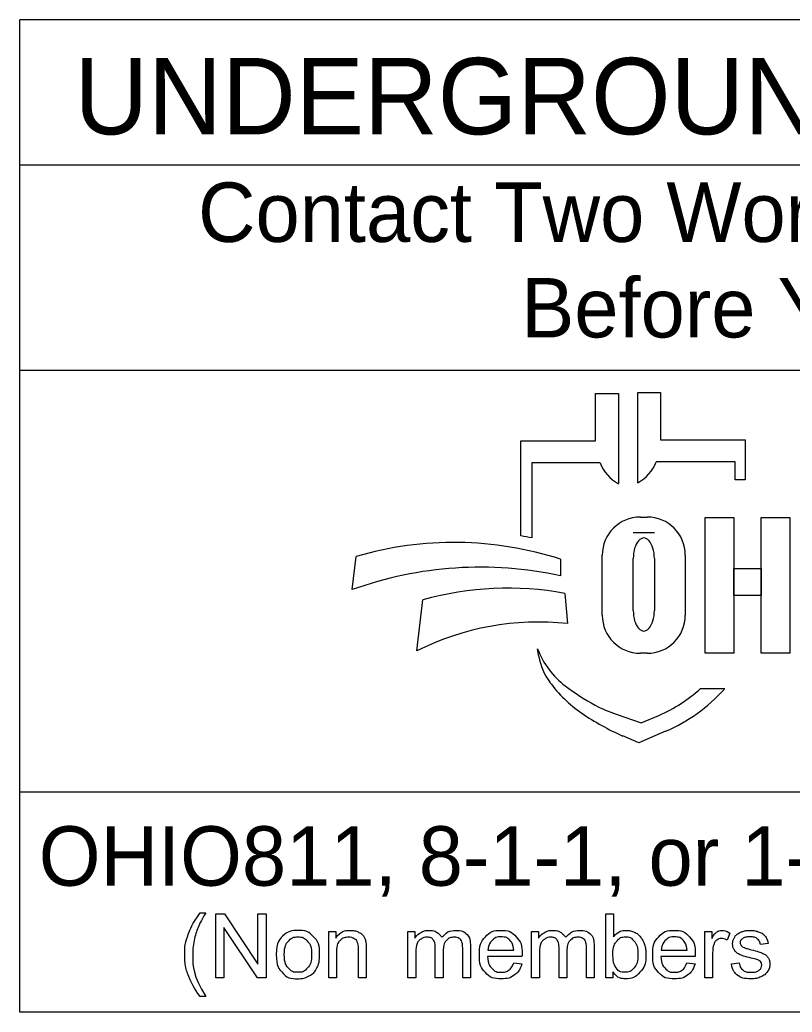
# Model space of a CAD drawing. Extents: x 0 to 42.4, y 0 to 22.
# Drawn here: x 3.947 to 5.766, y 2.954 to 5.292 of the extents above; entities that cross this region are included whole.
import ezdxf

# ---------------------------------------------------------------- set-up
doc = ezdxf.new("R2010")
doc.units = 0
doc.layers.add('SH_Data', color=7, linetype='Continuous')
doc.layers.add('SH_Text', color=7, linetype='Continuous')

msp = doc.modelspace()

# ---------------------------------------------------------------- linework, layer by layer
at = {"layer": 'SH_Data'}
for p, q in [((3.9472, 2.9543), (3.9472, 5.2918)), ((8.1972, 5.2918), (3.9472, 5.2918)), ((3.9472, 4.9502), (8.1972, 4.9502)), ((3.9472, 4.4668), (8.1972, 4.4668)), ((8.1972, 3.4721), (3.9472, 3.4721)), ((8.1972, 2.9543), (3.9472, 2.9543))]:
    msp.add_line(p, q, dxfattribs=at)
at = {"layer": 'SH_Text'}
for p, q in [((5.3032, 4.2998), (5.3032, 4.4112)), ((5.3032, 4.4112), (5.3569, 4.4112)), ((5.3569, 4.4112), (5.3569, 4.1992)), ((5.4026, 4.2015), (5.4026, 4.4136)), ((5.4026, 4.4136), (5.4562, 4.4136)), ((5.4562, 4.4136), (5.4562, 4.3021)), ((5.4562, 4.3021), (5.6554, 4.3021)), ((5.6554, 4.3021), (5.6554, 4.2083)), ((5.1273, 4.0759), (5.1273, 4.2998)), ((5.1273, 4.2998), (5.3032, 4.2998)), ((5.1525, 4.2483), (5.1525, 4.0715)), ((5.3136, 4.2483), (5.1525, 4.2483)), ((5.6321, 4.2506), (5.4458, 4.2506)), ((5.6321, 4.2083), (5.6321, 4.2506)), ((5.6554, 4.2083), (5.6321, 4.2083)), ((5.4082, 4.1206), (5.4248, 4.1206)), ((5.4415, 4.0836), (5.3917, 4.0836)), ((4.7299, 3.9496), (4.7393, 4.0277)), ((5.2206, 4.0212), (5.2206, 3.9824)), ((5.3188, 3.8891), (5.3188, 4.0311)), ((5.3917, 3.9005), (5.3917, 4.0228)), ((5.4415, 4.0228), (5.4415, 3.9005)), ((5.5142, 4.0311), (5.5142, 3.8891)), ((5.2305, 3.9406), (5.2368, 3.8696)), ((4.8817, 3.805), (4.8964, 3.9252)), ((5.1694, 3.7921), (5.1664, 3.8101)), ((5.4248, 3.7996), (5.4082, 3.7996)), ((5.5497, 3.7163), (5.6071, 3.7163)), ((5.3513, 3.6559), (5.4107, 3.6354)), ((5.4107, 3.6354), (5.4518, 3.6532)), ((5.4047, 3.5884), (5.3673, 3.6048)), ((5.468, 3.6158), (5.4047, 3.5884))]:
    msp.add_line(p, q, dxfattribs=at)
for points in [[(5.5607, 4.1195), (5.6286, 4.1195), (5.6286, 3.7996), (5.5607, 3.7996)], [(5.6928, 4.1195), (5.7608, 4.1195), (5.7608, 3.7996), (5.6928, 3.7996)], [(5.6286, 3.9996), (5.6928, 3.9996), (5.6928, 3.9356), (5.6286, 3.9356)]]:
    msp.add_lwpolyline(points, close=True, dxfattribs=at)
for points in [[(4.3718, 3.188), (4.385, 3.188)], [(4.4086, 3.0354), (4.4086, 3.1855), (4.4289, 3.1855), (4.5079, 3.0676), (4.5079, 3.1855), (4.5269, 3.1855), (4.5269, 3.0354), (4.5066, 3.0354), (4.4276, 3.1533), (4.4276, 3.0354), (4.4086, 3.0354)], [(5.344, 3.0354), (5.327, 3.0354), (5.327, 3.1855), (5.3454, 3.1855), (5.3454, 3.132)], [(4.6745, 3.0354), (4.6745, 3.1442), (4.6911, 3.1442), (4.6911, 3.1288)], [(4.8609, 3.0354), (4.8609, 3.1442), (4.8774, 3.1442), (4.8774, 3.1289)], [(5.1523, 3.0354), (5.1523, 3.1442), (5.1688, 3.1442), (5.1688, 3.1289)], [(5.5601, 3.0354), (5.5601, 3.1442), (5.5767, 3.1442), (5.5767, 3.1277)], [(5.6192, 3.1407), (5.6127, 3.1237)], [(5.0085, 3.1101), (5.0085, 3.0354), (4.99, 3.0354), (4.99, 3.1039)], [(5.2998, 3.1101), (5.2998, 3.0354), (5.2814, 3.0354), (5.2814, 3.1039)], [(5.7091, 3.1161), (5.691, 3.1137)], [(4.693, 3.0948), (4.693, 3.0354), (4.6745, 3.0354)], [(4.7629, 3.1023), (4.7629, 3.0354), (4.7445, 3.0354), (4.7445, 3.1015)], [(4.8794, 3.0918), (4.8794, 3.0354), (4.8609, 3.0354)], [(4.944, 3.0986), (4.944, 3.0354), (4.9256, 3.0354), (4.9256, 3.106)], [(5.0496, 3.1002), (5.1103, 3.1002)], [(5.1707, 3.0918), (5.1707, 3.0354), (5.1523, 3.0354)], [(5.2354, 3.0986), (5.2354, 3.0354), (5.217, 3.0354), (5.217, 3.106)], [(5.4576, 3.1002), (5.5183, 3.1002)], [(5.5785, 3.0924), (5.5785, 3.0354), (5.5601, 3.0354)], [(5.1297, 3.0851), (5.0485, 3.0851)], [(5.1101, 3.0705), (5.1292, 3.0681)], [(5.5377, 3.0851), (5.4565, 3.0851)], [(5.5181, 3.0705), (5.5372, 3.0681)], [(5.6227, 3.0679), (5.6409, 3.0707)], [(5.344, 3.049), (5.344, 3.0354)], [(4.385, 2.9912), (4.3718, 2.9912)]]:
    msp.add_lwpolyline(points, dxfattribs=at)
for centre, radius, start, end in [((5.405, 4.2851), 0.0985, 201.9296, 240.7469), ((5.3544, 4.2874), 0.0985, 299.2531, 338.0704), ((5.4082, 4.0311), 0.0895, 90, 180), ((5.4248, 4.0311), 0.0895, 0, 90), ((4.9992, 3.2669), 0.8191, 79.2074, 81.0007), ((4.9694, 3.2416), 0.8191, 72.1402, 106.3144), ((5.0325, 3.1105), 0.8919, 77.8238, 109.8274), ((5.0964, 3.2208), 0.7322, 79.44, 105.8467), ((5.4082, 3.8891), 0.0895, 180, 270), ((5.4248, 3.8891), 0.0895, 270, 0), ((5.1684, 3.2376), 0.6357, 83.8248, 116.8021), ((5.3538, 3.8822), 0.2008, 201.0457, 232.5314), ((5.3107, 3.8162), 0.1433, 189.6817, 216.0884), ((5.4444, 3.9137), 0.3088, 216.0884, 235.7167), ((5.5463, 4.1334), 0.5173, 232.5314, 241.794), ((5.3084, 3.9837), 0.3602, 293.4582, 312.0712), ((5.3084, 3.9837), 0.401, 293.4582, 317.8286), ((5.4611, 3.9746), 0.3371, 241.794, 250.9821), ((5.6109, 4.1579), 0.6044, 235.7167, 246.2325)]:
    msp.add_arc(centre, radius, start, end, dxfattribs=at)
for centre, start_param, end_param in [((5.4166, 4.0228), 4.712389, 7.853982), ((5.4166, 3.9005), 1.570796, 4.712389)]:
    msp.add_ellipse(centre, major_axis=(0, 0.0484), ratio=0.514403, start_param=start_param, end_param=end_param, dxfattribs=at)
for points in [[(4.3718, 2.9912), (4.3566, 3.0105), (4.346, 3.0363), (4.3354, 3.0621), (4.3354, 3.0897), (4.3354, 3.1141), (4.3433, 3.1364), (4.3526, 3.1623), (4.3718, 3.188)], [(4.385, 3.188), (4.3726, 3.1667), (4.3686, 3.1576), (4.3624, 3.1435), (4.3588, 3.1281), (4.3544, 3.109), (4.3544, 3.0896), (4.3544, 3.0404), (4.385, 2.9912)], [(4.551, 3.0898), (4.551, 3.12), (4.5678, 3.1345), (4.5819, 3.1466), (4.602, 3.1466), (4.6244, 3.1466), (4.6387, 3.1319), (4.6529, 3.1172), (4.6529, 3.0913), (4.6529, 3.0703), (4.6466, 3.0583), (4.6403, 3.0463), (4.6283, 3.0396), (4.6163, 3.033), (4.602, 3.033), (4.5792, 3.033), (4.5651, 3.0476), (4.551, 3.0623), (4.551, 3.0898)], [(4.6911, 3.1288), (4.7031, 3.1466), (4.7257, 3.1466), (4.7356, 3.1466), (4.7438, 3.1431), (4.752, 3.1396), (4.7561, 3.1338), (4.7602, 3.1281), (4.7619, 3.1202), (4.7629, 3.1151), (4.7629, 3.1023)], [(4.8774, 3.1289), (4.8825, 3.1369), (4.8911, 3.1417), (4.8996, 3.1466), (4.9104, 3.1466), (4.9225, 3.1466), (4.9302, 3.1416), (4.938, 3.1366), (4.9412, 3.1275), (4.9541, 3.1466), (4.9748, 3.1466), (4.991, 3.1466), (4.9997, 3.1377), (5.0085, 3.1287), (5.0085, 3.1101)], [(5.1292, 3.0681), (5.1247, 3.0514), (5.1125, 3.0422), (5.1003, 3.033), (5.0814, 3.033), (5.0575, 3.033), (5.0435, 3.0477), (5.0295, 3.0624), (5.0295, 3.0889), (5.0295, 3.1163), (5.0437, 3.1315), (5.0578, 3.1466), (5.0803, 3.1466), (5.1021, 3.1466), (5.116, 3.1318), (5.1298, 3.1169), (5.1298, 3.09), (5.1298, 3.0883), (5.1297, 3.0851)], [(5.1688, 3.1289), (5.1739, 3.1369), (5.1824, 3.1417), (5.1909, 3.1466), (5.2018, 3.1466), (5.2139, 3.1466), (5.2216, 3.1416), (5.2294, 3.1366), (5.2325, 3.1275), (5.2455, 3.1466), (5.2662, 3.1466), (5.2824, 3.1466), (5.2911, 3.1377), (5.2998, 3.1287), (5.2998, 3.1101)], [(5.3454, 3.132), (5.3571, 3.1466), (5.3752, 3.1466), (5.3852, 3.1466), (5.3942, 3.1426), (5.4032, 3.1385), (5.4089, 3.1312), (5.4147, 3.1239), (5.418, 3.1136), (5.4213, 3.1032), (5.4213, 3.0914), (5.4213, 3.0635), (5.4074, 3.0482), (5.3936, 3.033), (5.3743, 3.033), (5.355, 3.033), (5.344, 3.049)], [(5.5372, 3.0681), (5.5327, 3.0514), (5.5205, 3.0422), (5.5083, 3.033), (5.4893, 3.033), (5.4655, 3.033), (5.4515, 3.0477), (5.4375, 3.0624), (5.4375, 3.0889), (5.4375, 3.1163), (5.4517, 3.1315), (5.4658, 3.1466), (5.4883, 3.1466), (5.5101, 3.1466), (5.524, 3.1318), (5.5378, 3.1169), (5.5378, 3.09), (5.5378, 3.0883), (5.5377, 3.0851)], [(5.5767, 3.1277), (5.583, 3.1393), (5.5884, 3.1429), (5.5938, 3.1466), (5.6002, 3.1466), (5.6095, 3.1466), (5.6192, 3.1407)], [(5.6409, 3.0707), (5.6424, 3.0598), (5.6495, 3.0539), (5.6565, 3.0481), (5.6692, 3.0481), (5.6819, 3.0481), (5.6881, 3.0533), (5.6942, 3.0584), (5.6942, 3.0654), (5.6942, 3.0717), (5.6888, 3.0753), (5.685, 3.0777), (5.6699, 3.0815), (5.6496, 3.0866), (5.6417, 3.0904), (5.6339, 3.0941), (5.6298, 3.1007), (5.6258, 3.1073), (5.6258, 3.1153), (5.6258, 3.1226), (5.6291, 3.1288), (5.6325, 3.135), (5.6382, 3.139), (5.6425, 3.1422), (5.65, 3.1444), (5.6574, 3.1466), (5.6659, 3.1466), (5.6787, 3.1466), (5.6884, 3.1429), (5.6981, 3.1392), (5.7027, 3.1329), (5.7074, 3.1266), (5.7091, 3.1161)], [(4.57, 3.0898), (4.57, 3.0689), (4.5791, 3.0585), (4.5882, 3.0481), (4.602, 3.0481), (4.6157, 3.0481), (4.6248, 3.0585), (4.6339, 3.069), (4.6339, 3.0904), (4.6339, 3.1106), (4.6248, 3.121), (4.6156, 3.1314), (4.602, 3.1314), (4.5882, 3.1314), (4.5791, 3.1211), (4.57, 3.1107), (4.57, 3.0898)], [(4.7445, 3.1015), (4.7445, 3.1128), (4.7423, 3.1184), (4.7402, 3.1239), (4.7347, 3.1273), (4.7292, 3.1306), (4.7218, 3.1306), (4.7101, 3.1306), (4.7015, 3.1231), (4.693, 3.1157), (4.693, 3.0948)], [(4.9256, 3.106), (4.9256, 3.1183), (4.9211, 3.1245), (4.9166, 3.1306), (4.9063, 3.1306), (4.8985, 3.1306), (4.8919, 3.1265), (4.8853, 3.1224), (4.8823, 3.1145), (4.8794, 3.1066), (4.8794, 3.0918)], [(4.99, 3.1039), (4.99, 3.1149), (4.9882, 3.1198), (4.9864, 3.1247), (4.9817, 3.1276), (4.977, 3.1306), (4.9707, 3.1306), (4.9592, 3.1306), (4.9516, 3.123), (4.944, 3.1153), (4.944, 3.0986)], [(5.1103, 3.1002), (5.1091, 3.1139), (5.1034, 3.1208), (5.0946, 3.1315), (5.0805, 3.1315), (5.0678, 3.1315), (5.0591, 3.123), (5.0505, 3.1144), (5.0496, 3.1002)], [(5.217, 3.106), (5.217, 3.1183), (5.2125, 3.1245), (5.208, 3.1306), (5.1977, 3.1306), (5.1899, 3.1306), (5.1833, 3.1265), (5.1767, 3.1224), (5.1737, 3.1145), (5.1707, 3.1066), (5.1707, 3.0918)], [(5.2814, 3.1039), (5.2814, 3.1149), (5.2796, 3.1198), (5.2778, 3.1247), (5.2731, 3.1276), (5.2684, 3.1306), (5.262, 3.1306), (5.2506, 3.1306), (5.243, 3.123), (5.2354, 3.1153), (5.2354, 3.0986)], [(5.3438, 3.0906), (5.3438, 3.071), (5.3491, 3.0623), (5.3578, 3.0481), (5.3726, 3.0481), (5.3847, 3.0481), (5.3935, 3.0586), (5.4023, 3.0691), (5.4023, 3.0899), (5.4023, 3.1112), (5.3938, 3.1214), (5.3854, 3.1315), (5.3734, 3.1315), (5.3614, 3.1315), (5.3526, 3.121), (5.3438, 3.1105), (5.3438, 3.0906)], [(5.5183, 3.1002), (5.5171, 3.1139), (5.5114, 3.1208), (5.5025, 3.1315), (5.4885, 3.1315), (5.4758, 3.1315), (5.4671, 3.123), (5.4585, 3.1144), (5.4576, 3.1002)], [(5.6127, 3.1237), (5.606, 3.1276), (5.5992, 3.1276), (5.5932, 3.1276), (5.5884, 3.124), (5.5836, 3.1203), (5.5816, 3.1139), (5.5785, 3.1041), (5.5785, 3.0924)], [(5.691, 3.1137), (5.6898, 3.1221), (5.6839, 3.1268), (5.678, 3.1315), (5.6672, 3.1315), (5.6545, 3.1315), (5.6491, 3.1273), (5.6436, 3.1231), (5.6436, 3.1175), (5.6436, 3.1139), (5.6459, 3.111), (5.6482, 3.108), (5.653, 3.1061), (5.6557, 3.105), (5.6693, 3.1013), (5.6889, 3.0961), (5.6966, 3.0928), (5.7044, 3.0895), (5.7088, 3.0831), (5.7132, 3.0768), (5.7132, 3.0674), (5.7132, 3.0582), (5.7078, 3.05), (5.7024, 3.0419), (5.6923, 3.0374), (5.6821, 3.033), (5.6693, 3.033), (5.648, 3.033), (5.6369, 3.0418), (5.6258, 3.0506), (5.6227, 3.0679)], [(5.0485, 3.0851), (5.0496, 3.0671), (5.0587, 3.0576), (5.0678, 3.0481), (5.0814, 3.0481), (5.0916, 3.0481), (5.0988, 3.0534), (5.1059, 3.0588), (5.1101, 3.0705)], [(5.4565, 3.0851), (5.4576, 3.0671), (5.4667, 3.0576), (5.4758, 3.0481), (5.4894, 3.0481), (5.4996, 3.0481), (5.5067, 3.0534), (5.5139, 3.0588), (5.5181, 3.0705)]]:
    msp.add_open_spline(points, degree=3, dxfattribs=at)

# ---------------------------------------------------------------- texts
for s, height, p in [('UNDERGROUND UTILITIES', 0.18, (4.0754, 5.0221)), ('Contact Two Working Days', 0.14, (4.3669, 4.7686)), ('Before You Dig', 0.14, (5.128, 4.5436)), ('OHIO811, 8-1-1, or 1-800-362-2764', 0.14, (3.9917, 3.2521))]:
    msp.add_text(s, height=height, dxfattribs=at).set_placement(p)

doc.saveas('drawing.dxf')
